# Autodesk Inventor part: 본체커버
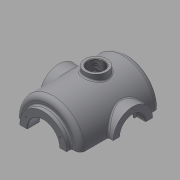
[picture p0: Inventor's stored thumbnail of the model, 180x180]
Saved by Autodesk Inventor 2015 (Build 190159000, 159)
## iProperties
Created: 2016-02
Part Number: 본체커버
Material: 일반
Document SubType Name: Modeling
Designer: mduedu
Density: 2.71 g/cm^3
Appearance: 기본값
Author: mduedu
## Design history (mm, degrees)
sketch "스케치2"
  geometry: L1 (0, 90)-(0, -90); L2 (65, -65.993)-(65, 90); L3 (65, 90)-(0, 90); A1 r 100 centre (0, 10) between (0, -90) and (65, -65.993); 2 further points
  constraints: 6 end point, 2 point on circle, 1 centre point, 1 coincident, 1 horizontal, 1 midpoint, 1 parallel, 1 point on line, 1 vertical
  dimensions: "d3" = 180 distance of L1.start L1.end; "d5" = 130 diameter of L2 L1; "d6" = 100 radius of A1
revolve "회전1" sketch "스케치2" stored, may be unused: angle "d7" = 90 deg
sketch "스케치3"
  geometry: C1 r 47.5 at (0, 0); 1 further point
  constraints: 1 centre point, 1 coincident
  dimensions: "d8" = 95 diameter of C1
extrude "돌출2" join sketch "스케치3" distance "d10" = 10; taper "d11" = 0 deg
sketch "스케치5"
  geometry: L1 (47.5, 100)-(47.5, 90) reference; L2 (47.5, 90)-(65, 90) reference; L3 (65, 90)-(65, -65.993) reference; L4 (-65, -65.993)-(-65, 90) reference; L5 (-65, 90)-(-47.5, 90) reference; L6 (-47.5, 90)-(-47.5, 100) reference; L7 (-47.5, 100)-(47.5, 100) reference; L8 (55, 75)-(55, -61.239); L9 (0, 75)-(55, 75); L10 (0, 75)-(0, -80); A1 r 100 centre (0, 10) between (-65, -65.993) and (0, -90) reference; A2 r 100 centre (0, 10) between (0, -90) and (65, -65.993) reference; A3 r 90 centre (0, 10) between (0, -80) and (55, -61.239); 1 further point
  constraints: 6 end point, 2 point on circle, 1 centre point, 1 parallel, 1 perpendicular, 1 point on line, 1 vertical
  dimensions: "d13" = 10 distance between parallel lines of L3 L8; "d14" = 10 radial gap between concentric circles of A3 A1; "d15" = 15 distance between parallel lines of L9 L2
revolve "회전2" sketch "스케치5" stored, may be unused: angle "d16" = 90 deg
hole "구멍1" diameter "d19" = 65; stored, may be unused: countersink angle "d23" = 90 deg, drill point angle "d25" = 118 deg; dims "d17" = 10, "d18" = 10, "d20" = 6, "d21" = 4, "d22" = 2, "d24" = 8
node "작업 평면1"
sketch "스케치6"
  geometry: L1 (47.5, 100)-(-47.5, 100) reference; C1 r 40 at (0, -7); 1 further point
  constraints: 1 centre point, 1 vertical alignment
  dimensions: "d27" = 80 diameter of C1; "d29" = 107 distance from line of C1.centre L1
extrude "돌출3" join sketch "스케치6" stored distance "d30" = 10; taper "d31" = 0 deg
hole "구멍2" diameter "d34" = 42; stored, may be unused: countersink angle "d38" = 90 deg, drill point angle "d40" = 118 deg; dims "d32" = 10, "d33" = 10, "d35" = 6, "d36" = 52, "d37" = 18, "d39" = 8
sketch "스케치7" dims "d41" = 65
  geometry: C1 r 40 at (0, 0) reference; 3 further points
  constraints: 2 vertical alignment, 1 coincident, 2 other
hole "구멍3" sketch "스케치7" at (0, 32.5) diameter "d43" = 3.242; stored, may be unused: countersink angle "d47" = 90 deg, drill point angle "d49" = 118 deg; dims "d44" = 11, "d45" = 13, "d46" = 18, "d48" = 13
sketch "스케치8" dims "d53" = 80
  geometry: 3 further points
  constraints: 2 vertical alignment, 1 coincident, 2 other
hole "구멍4" sketch "스케치8" at (0, -40) diameter "d56" = 3.242; stored, may be unused: countersink angle "d60" = 90 deg, drill point angle "d62" = 118 deg; dims "d57" = 11, "d58" = 13, "d59" = 18, "d61" = 13
fillet "모깎기1" dims "d66" = 10
fillet "모깎기2" dims "d67" = 3
fillet "모깎기3" dims "d68" = 0.3
chamfer "모따기1" distance "d69" = 1; stored, may be unused: second distance "d70" = 2, angle "d71" = 45 deg
node "작업 평면5"
sketch "스케치10"
  geometry: L1 (-50, 66)-(50, 66); L2 (50, 66)-(50, 50); L3 (50, 50)-(-50, 50); L4 (-50, 50)-(-50, 66); 2 further points
  constraints: 8 end point, 2 horizontal, 2 vertical, 1 midpoint, 1 vertical alignment
  dimensions: "d177" = 50 distance from line of L3 point (0, 0); "d178" = 100 distance of L1.start L1.end; "d179" = 16 distance of L3.end L1.start
extrude "돌출5" join sketch "스케치10" stored distance "d84" = 10; taper "d85" = 0 deg
sketch "스케치21" dims "d180" = 220, "d182" = 130
  geometry: L1 (65, 58)-(-65, 58); L2 (-65, 58)-(-65, -32); L3 (-65, -32)-(65, -32); L4 (65, -32)-(65, 58); L5 (50, 50)-(50, 66) reference; 4 further points
  constraints: 8 end point, 3 horizontal alignment, 3 midpoint, 2 parallel, 1 horizontal, 1 perpendicular, 1 vertical alignment, 4 other
extrude "돌출13" join sketch "스케치21" distance "d183" = 10; taper "d184" = 0 deg
sketch "스케치11"
  geometry: L1 (-65, 80)-(-65, -61.239) reference; L2 (-100, -97)-(-100, -32) reference; L3 (-65, -42.793)-(-100, -63); L4 (-100, -97)-(-110, -97) reference; 1 further point
  constraints: 2 end point, 2 point on line
  dimensions: "d185" = 34 distance from line of L3.end L4; "d186" = 120 deg angle of L2 L3
feature "리브1" sketch "스케치11" dims "d88" = 1, "d89" = 16, "d90" = 0, "d91" = 0, "d92" = 1, "d93" = 1
fillet "모깎기12"
fillet "모깎기13"
fillet "모깎기16" dims "d167" = 3
fillet "모깎기18"
fillet "모깎기17" dims "d168" = 3
fillet "모깎기19" dims "d187" = 3
node "작업 평면6"
sketch "스케치19"
  geometry: L1 (75, -47)-(75, 33) reference; L2 (-75, -47)-(-75, 33) reference; L3 (75, -7)-(-75, -7); C1 r 22.5 at (0, -7); 1 further point
  constraints: 3 midpoint, 2 end point, 1 centre point
  dimensions: "d149" = 45 diameter of C1
extrude "돌출11" join sketch "스케치19" stored distance "d150" = 10; taper "d151" = 0 deg
hole "구멍6" diameter "d154" = 33.376; stored, may be unused: countersink angle "d158" = 90 deg, drill point angle "d160" = 118 deg; dims "d155" = 6, "d156" = 4, "d157" = 2, "d159" = 8, "d190" = 10, "d191" = 10
fillet "모깎기11" dims "d161" = 3
chamfer "모따기3" distance "d164" = 1; stored, may be unused: second distance "d165" = 2, angle "d166" = 45 deg
sketch "스케치22" dims "d189" = 20
  geometry: L1 (-10, -123)-(10, -123); L2 (10, -123)-(10, -103); L3 (10, -103)-(-10, -103); L4 (-10, -103)-(-10, -123); A1 r 65 centre (0, -58) between (-65, -58) and (65, -58) reference; 2 further points
  constraints: 8 end point, 2 parallel, 1 horizontal, 1 horizontal alignment, 1 midpoint, 1 perpendicular, 1 tangent, 1 vertical alignment, 2 other
  dimensions: "d193" = 30 dimension on L1
extrude "돌출14" cut sketch "스케치22" stored distance "d194" = 10; taper "d195" = 0 deg
fillet "모깎기21" dims "d196" = 3
feature "분할1"
node "솔리드2"
pattern_circular "원형 패턴1" dims angle "d51" = 360 deg
mirror "대칭1"
pattern_circular "원형 패턴2" dims angle "d64" = 360 deg
node "절단 모서리 투영1"
other parameters: "d26" = 75, "d136" = 175
